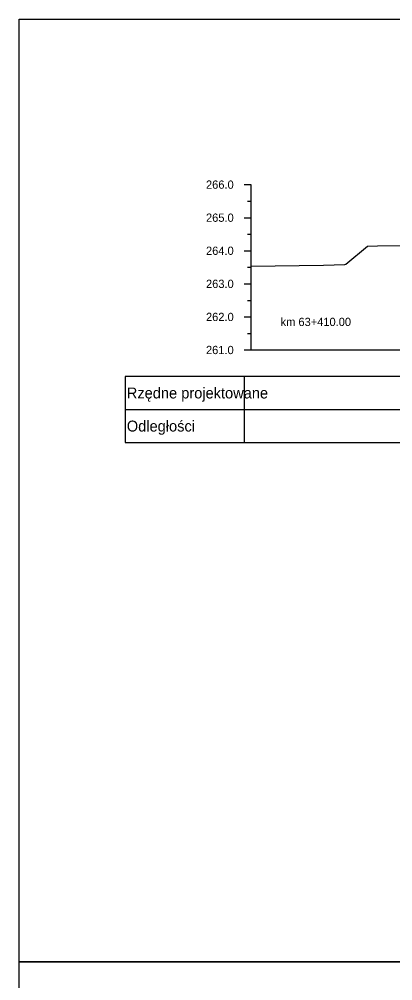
# Model space of a CAD drawing. Extents: x -1 to 65640748, y -22 to 5530284.
# Drawn here: x 2476.33 to 2487.61, y 994.37 to 1023.44 of the extents above; entities that cross this region are included whole.
import ezdxf

# ---------------------------------------------------------------- set-up
doc = ezdxf.new("R2010")
doc.units = 0
for name, color, linetype in [('IR_cross_section', 7, 'Continuous'), ('IR_cross_section_tytul', 7, 'Continuous'), ('IR_default', 7, 'Continuous'), ('TOR_PRZEK_P-tabelka projektowane', 7, 'Continuous'), ('TOR_PRZEK_P-teren istniejacy', 7, 'Continuous'), ('TOR_PRZEK_P-uklad odniesienia', 7, 'Continuous')]:
    doc.layers.add(name, color=color, linetype=linetype)

msp = doc.modelspace()

# ---------------------------------------------------------------- linework, layer by layer
at = {"layer": 'IR_cross_section'}
for points in [[(2476.328, 1023.438), (2676.328, 1023.438), (2676.328, 994.938), (2476.328, 994.938)], [(2476.328, 994.938), (2676.328, 994.938), (2676.328, 966.438), (2476.328, 966.438)]]:
    msp.add_lwpolyline(points, close=True, dxfattribs=at)
at = {"layer": 'IR_default'}
for points in [[(2486.851, 1016.573), (2486.85, 1016.573), (2486.851, 1016.573), (2486.85, 1016.572), (2486.851, 1016.573), (2486.851, 1016.572), (2486.851, 1016.573), (2486.851, 1016.573)], [(2486.17, 1016.018), (2486.169, 1016.019), (2486.17, 1016.018), (2486.169, 1016.018), (2486.17, 1016.018), (2486.17, 1016.018), (2486.17, 1016.018), (2486.17, 1016.019)]]:
    msp.add_lwpolyline(points, dxfattribs=at)
at = {"layer": 'TOR_PRZEK_P-tabelka projektowane'}
for p, q in [((2479.528, 1012.638), (2479.528, 1010.638)), ((2483.128, 1012.638), (2483.128, 1010.638)), ((2479.528, 1011.638), (2513.328, 1011.638))]:
    msp.add_line(p, q, dxfattribs=at)
msp.add_lwpolyline([(2479.528, 1012.638), (2479.528, 1010.638), (2513.328, 1010.638), (2513.328, 1012.638)], close=True, dxfattribs=at)
at = {"layer": 'TOR_PRZEK_P-teren istniejacy'}
msp.add_lwpolyline([(2483.328, 1015.969), (2485.518, 1016.002), (2486.17, 1016.018), (2486.197, 1016.036), (2486.851, 1016.573), (2487.15, 1016.583), (2488.845, 1016.599)], dxfattribs=at)
at = {"layer": 'TOR_PRZEK_P-uklad odniesienia'}
for p, q in [((2483.128, 1018.438), (2483.328, 1018.438)), ((2483.328, 1018.438), (2483.328, 1013.438)), ((2483.228, 1017.938), (2483.328, 1017.938)), ((2483.128, 1017.438), (2483.328, 1017.438)), ((2483.228, 1016.938), (2483.328, 1016.938)), ((2483.128, 1016.438), (2483.328, 1016.438)), ((2483.228, 1015.938), (2483.328, 1015.938)), ((2483.128, 1015.438), (2483.328, 1015.438)), ((2483.228, 1014.938), (2483.328, 1014.938)), ((2483.128, 1014.438), (2483.328, 1014.438)), ((2483.228, 1013.938), (2483.328, 1013.938)), ((2483.128, 1013.438), (2483.328, 1013.438)), ((2483.328, 1013.438), (2513.328, 1013.438))]:
    msp.add_line(p, q, dxfattribs=at)

# ---------------------------------------------------------------- texts
at = {"layer": 'IR_cross_section_tytul'}
msp.add_text('km 63+410.00', height=0.25, dxfattribs=at).set_placement((2484.225, 1014.163))
at = {"layer": 'TOR_PRZEK_P-tabelka projektowane'}
for s, p in [('Rzędne projektowane', (2479.578, 1011.973)), ('Odległości', (2479.578, 1010.973))]:
    msp.add_text(s, height=0.33, dxfattribs=at).set_placement(p)
at = {"layer": 'TOR_PRZEK_P-uklad odniesienia'}
for s, p in [('266.0', (2481.971, 1018.313)), ('265.0', (2481.971, 1017.313)), ('264.0', (2481.971, 1016.313)), ('263.0', (2481.971, 1015.313)), ('262.0', (2481.971, 1014.313)), ('261.0', (2481.971, 1013.313))]:
    msp.add_text(s, height=0.25, dxfattribs=at).set_placement(p)

doc.saveas('drawing.dxf')
